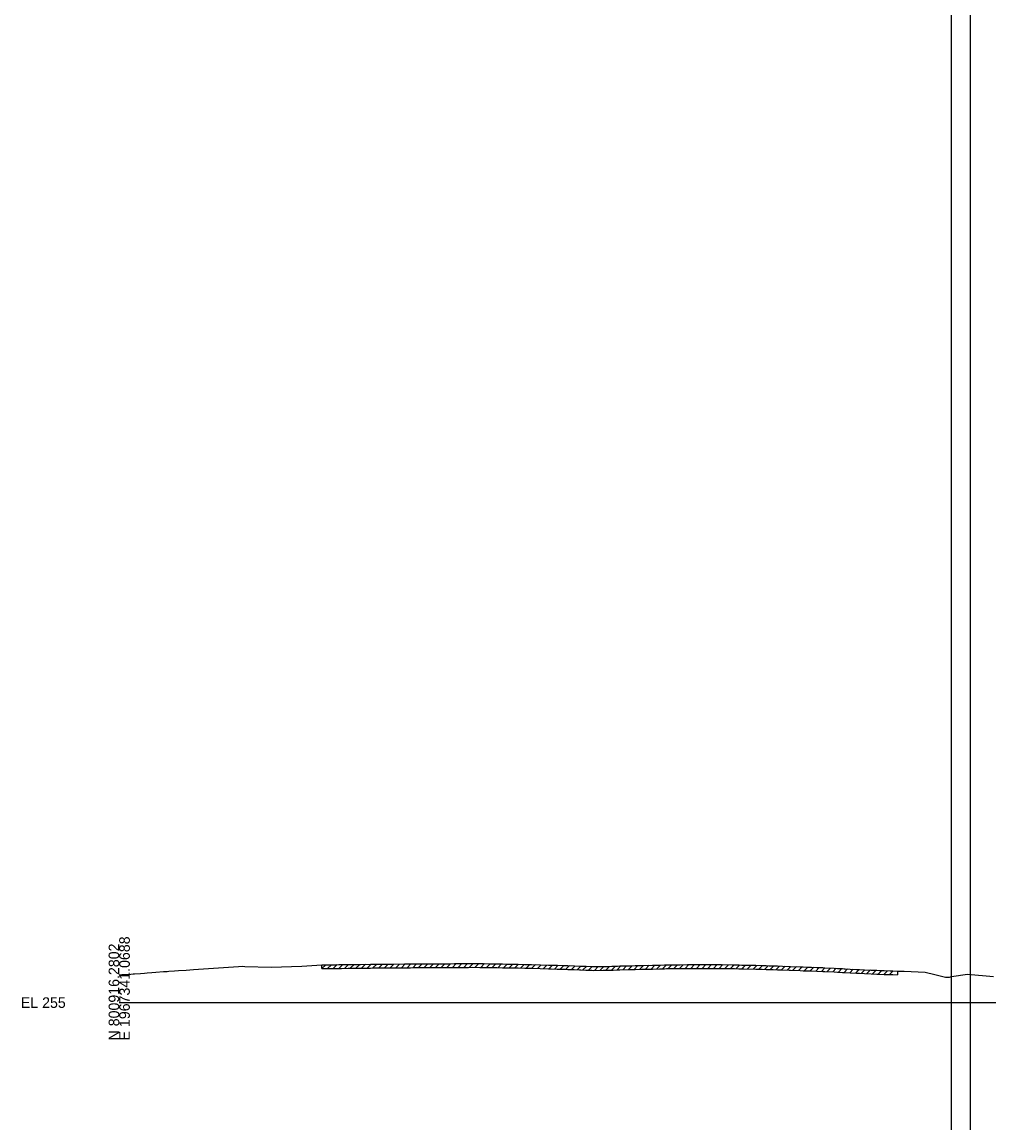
# Model space of a CAD drawing. Extents: x -119 to 6018, y -82 to 34226.
# Drawn here: x -25.7 to 229.9, y 22468.2 to 22759.1 of the extents above; entities that cross this region are included whole.
import ezdxf

# ---------------------------------------------------------------- set-up
doc = ezdxf.new("R2010")
doc.units = 0
for name, color, linetype in [('Default', 7, 'Continuous'), ('RD_GPK_XS_Cell', 7, 'Continuous'), ('RD_Sketch1', 7, 'Continuous'), ('RD_XS_ExGround', 7, 'Continuous'), ('RD_XS_ExPaveRet', 7, 'Continuous')]:
    doc.layers.add(name, color=color, linetype=linetype)

msp = doc.modelspace()

# ---------------------------------------------------------------- linework, layer by layer
at = {"layer": 'RD_GPK_XS_Cell'}
msp.add_line((0, 22500), (300, 22500), dxfattribs=at)
at = {"layer": 'RD_Sketch1'}
for p, q in [((220, -82), (220, 34226.15)), ((225, -82), (225, 34226.15))]:
    msp.add_line(p, q, dxfattribs=at)
at = {"layer": 'RD_XS_ExGround'}
msp.add_lwpolyline([(0, 22507.36), (0.69, 22507.4), (3.08, 22507.55), (3.68, 22507.59), (4, 22507.61), (5.6, 22507.73), (6.65, 22507.81), (7.42, 22507.86), (8.58, 22507.95), (9.66, 22508.04), (11.72, 22508.18), (12.64, 22508.25), (13.13, 22508.28), (14.64, 22508.39), (15.63, 22508.45), (17.67, 22508.59), (18.66, 22508.66), (19.61, 22508.73), (20.98, 22508.82), (31.51, 22509.54), (32.52, 22509.59), (33.24, 22509.57), (40.17, 22509.35), (48.3, 22509.59), (53.57, 22509.98), (53.9, 22509.97), (54.64, 22509.99), (57.52, 22510.02), (58.01, 22510.03), (58.78, 22510.04), (60.48, 22510.06), (61.59, 22510.07), (63.75, 22510.09), (66.39, 22510.14), (66.98, 22510.16), (67.55, 22510.16), (68.69, 22510.18), (69.38, 22510.18), (70.61, 22510.18), (72.45, 22510.18), (75.37, 22510.21), (76.97, 22510.22), (77.8, 22510.24), (78.34, 22510.24), (79.62, 22510.26), (81.53, 22510.26), (84.3, 22510.27), (86.05, 22510.27), (87.3, 22510.28), (88.62, 22510.29), (90.71, 22510.31), (92.3, 22510.32), (93.31, 22510.33), (95.31, 22510.32), (96.29, 22510.3), (98.03, 22510.27), (99.18, 22510.25), (99.84, 22510.24), (101.29, 22510.22), (102.31, 22510.2), (103.18, 22510.18), (104.41, 22510.17), (105.42, 22510.15), (107.18, 22510.11), (108.31, 22510.09), (108.96, 22510.07), (111.21, 22509.99), (113.49, 22509.92), (114.16, 22509.9), (115.75, 22509.86), (117.31, 22509.81), (117.75, 22509.8), (118.54, 22509.79), (120.26, 22509.72), (121.61, 22509.67), (122.02, 22509.64), (123.29, 22509.61), (124.93, 22509.54), (125.29, 22509.51), (127.89, 22509.54), (128.31, 22509.55), (129.37, 22509.58), (130.18, 22509.6), (130.57, 22509.61), (131.68, 22509.67), (132.29, 22509.68), (134.48, 22509.73), (134.9, 22509.74), (135.52, 22509.76), (136.34, 22509.77), (138.11, 22509.81), (140.96, 22509.88), (142.81, 22509.92), (144.1, 22509.95), (144.64, 22509.97), (145.43, 22509.98), (147.09, 22510.01), (148.22, 22510.02), (150.19, 22510.03), (150.59, 22510.03), (153.04, 22510.04), (154.61, 22510.04), (155.46, 22510.04), (156.01, 22510.05), (157.31, 22510.05), (159.2, 22510.05), (161.98, 22509.99), (162.65, 22509.98), (163.73, 22509.95), (164.59, 22509.93), (165.09, 22509.92), (168.22, 22509.85), (169.93, 22509.8), (171, 22509.78), (171.76, 22509.76), (172.86, 22509.73), (174, 22509.69), (175.29, 22509.64), (177.09, 22509.57), (177.39, 22509.56), (179.94, 22509.47), (180.73, 22509.44), (181.91, 22509.4), (182.56, 22509.37), (182.95, 22509.36), (184.34, 22509.31), (185.99, 22509.24), (186.52, 22509.22), (188.94, 22509.09), (189.84, 22509.04), (191.12, 22508.97), (191.56, 22508.94), (191.87, 22508.93), (193.19, 22508.86), (194.87, 22508.77), (195.18, 22508.76), (195.67, 22508.74), (197.01, 22508.68), (198.76, 22508.61), (200.23, 22508.54), (200.97, 22508.51), (202.15, 22508.47), (203.75, 22508.41), (204.45, 22508.39), (205.71, 22508.33), (207.48, 22508.3), (213.02, 22508.04), (215.52, 22507.41), (218.4, 22506.7), (219.42, 22506.7), (219.96, 22506.87), (224.19, 22507.48), (231.1, 22506.89)], dxfattribs=at)
at = {"layer": 'RD_XS_ExPaveRet'}
for p, q in [((53.57, 22508.98), (54.58, 22509.98)), ((53.57, 22508.98), (53.57, 22509.98)), ((55.07, 22508.99), (56.09, 22510.01)), ((56.57, 22509.01), (57.59, 22510.03)), ((58.07, 22509.03), (59.08, 22510.04)), ((59.57, 22509.05), (60.58, 22510.06)), ((61.07, 22509.06), (62.08, 22510.07)), ((62.57, 22509.08), (63.58, 22510.09)), ((64.07, 22509.1), (65.09, 22510.12)), ((65.57, 22509.13), (66.59, 22510.15)), ((67.07, 22509.16), (68.08, 22510.17)), ((68.57, 22509.18), (69.57, 22510.18)), ((70.07, 22509.18), (71.07, 22510.18)), ((71.57, 22509.18), (72.58, 22510.18)), ((73.07, 22509.19), (74.08, 22510.19)), ((74.57, 22509.2), (75.58, 22510.21)), ((76.07, 22509.21), (77.08, 22510.23)), ((77.57, 22509.23), (78.58, 22510.25)), ((79.07, 22509.25), (80.08, 22510.26)), ((80.57, 22509.26), (81.57, 22510.26)), ((82.07, 22509.26), (83.07, 22510.27)), ((83.57, 22509.27), (84.57, 22510.27)), ((85.07, 22509.27), (86.08, 22510.27)), ((86.57, 22509.28), (87.58, 22510.28)), ((88.07, 22509.29), (89.08, 22510.3)), ((89.57, 22509.3), (90.58, 22510.31)), ((91.07, 22509.31), (92.08, 22510.32)), ((92.57, 22509.33), (93.58, 22510.33)), ((94.07, 22509.33), (95.07, 22510.32)), ((95.57, 22509.32), (96.55, 22510.3)), ((97.07, 22509.29), (98.05, 22510.27)), ((98.57, 22509.26), (99.55, 22510.24)), ((100.07, 22509.23), (101.06, 22510.22)), ((101.57, 22509.21), (102.56, 22510.19)), ((103.07, 22509.19), (104.06, 22510.17)), ((104.57, 22509.16), (105.55, 22510.15)), ((106.07, 22509.13), (107.05, 22510.11)), ((107.57, 22509.1), (108.55, 22510.08)), ((109.07, 22509.06), (110.04, 22510.03)), ((110.57, 22509.01), (111.54, 22509.98)), ((143.57, 22508.94), (144.6, 22509.97)), ((145.07, 22508.98), (146.09, 22509.99)), ((146.57, 22509), (147.58, 22510.01)), ((148.07, 22509.02), (149.08, 22510.02)), ((149.57, 22509.03), (150.58, 22510.03)), ((151.07, 22509.03), (152.07, 22510.04)), ((152.57, 22509.04), (153.57, 22510.04)), ((154.07, 22509.04), (155.07, 22510.04)), ((155.57, 22509.04), (156.57, 22510.05)), ((157.07, 22509.05), (158.07, 22510.05)), ((158.57, 22509.05), (159.56, 22510.04)), ((160.07, 22509.03), (161.05, 22510.01)), ((161.57, 22509), (162.55, 22509.98)), ((53.57, 22508.98), (53.9, 22508.97)), ((53.9, 22508.97), (54.64, 22508.99)), ((54.64, 22508.99), (57.52, 22509.02)), ((57.52, 22509.02), (58.01, 22509.03)), ((58.01, 22509.03), (58.78, 22509.04)), ((58.78, 22509.04), (60.48, 22509.06)), ((60.48, 22509.06), (61.59, 22509.07)), ((61.59, 22509.07), (63.75, 22509.09)), ((63.75, 22509.09), (66.39, 22509.14)), ((66.39, 22509.14), (66.98, 22509.16)), ((66.98, 22509.16), (67.55, 22509.16)), ((67.55, 22509.16), (68.69, 22509.18)), ((68.69, 22509.18), (69.38, 22509.18)), ((69.38, 22509.18), (70.61, 22509.18)), ((70.61, 22509.18), (72.45, 22509.18)), ((72.45, 22509.18), (75.37, 22509.21)), ((75.37, 22509.21), (76.97, 22509.22)), ((76.97, 22509.22), (77.8, 22509.24)), ((77.8, 22509.24), (78.34, 22509.24)), ((78.34, 22509.24), (79.62, 22509.26)), ((79.62, 22509.26), (81.53, 22509.26)), ((81.53, 22509.26), (84.3, 22509.27)), ((84.3, 22509.27), (86.05, 22509.27)), ((86.05, 22509.27), (87.3, 22509.28)), ((87.3, 22509.28), (88.62, 22509.29)), ((88.62, 22509.29), (90.71, 22509.31)), ((90.71, 22509.31), (92.3, 22509.32)), ((92.3, 22509.32), (93.31, 22509.33)), ((93.31, 22509.33), (95.31, 22509.32)), ((95.31, 22509.32), (96.29, 22509.3)), ((96.29, 22509.3), (98.03, 22509.27)), ((98.03, 22509.27), (99.18, 22509.25)), ((99.18, 22509.25), (99.84, 22509.24)), ((99.84, 22509.24), (101.29, 22509.21)), ((101.29, 22509.21), (102.31, 22509.2)), ((102.31, 22509.2), (103.18, 22509.18)), ((103.18, 22509.18), (104.41, 22509.17)), ((104.41, 22509.17), (105.42, 22509.15)), ((105.42, 22509.15), (107.18, 22509.11)), ((107.18, 22509.11), (108.31, 22509.09)), ((108.31, 22509.09), (108.96, 22509.07)), ((108.96, 22509.07), (111.21, 22508.99)), ((111.21, 22508.99), (113.49, 22508.92)), ((112.07, 22508.96), (113.04, 22509.93)), ((113.49, 22508.92), (114.16, 22508.9)), ((113.57, 22508.91), (114.54, 22509.89)), ((114.16, 22508.9), (115.75, 22508.86)), ((115.07, 22508.87), (116.05, 22509.85)), ((115.75, 22508.86), (117.31, 22508.81)), ((116.57, 22508.83), (117.54, 22509.81)), ((117.31, 22508.81), (117.75, 22508.8)), ((117.75, 22508.8), (118.54, 22508.79)), ((118.07, 22508.8), (119.04, 22509.77)), ((118.54, 22508.79), (120.26, 22508.72)), ((119.57, 22508.75), (120.54, 22509.71)), ((120.26, 22508.72), (121.61, 22508.67)), ((121.07, 22508.69), (122.02, 22509.64)), ((121.61, 22508.67), (122.02, 22508.64)), ((122.02, 22508.64), (123.29, 22508.61)), ((122.57, 22508.62), (123.55, 22509.6)), ((123.29, 22508.61), (124.93, 22508.54)), ((124.07, 22508.58), (125.03, 22509.53)), ((124.93, 22508.54), (125.29, 22508.51)), ((125.29, 22508.51), (127.89, 22508.54)), ((125.57, 22508.51), (126.58, 22509.52)), ((127.07, 22508.53), (128.08, 22509.54)), ((127.89, 22508.54), (128.31, 22508.55)), ((128.31, 22508.55), (129.37, 22508.58)), ((128.57, 22508.55), (129.6, 22509.58)), ((129.37, 22508.58), (130.18, 22508.6)), ((130.07, 22508.59), (131.12, 22509.64)), ((130.18, 22508.6), (130.57, 22508.61)), ((130.57, 22508.61), (131.68, 22508.67)), ((131.57, 22508.66), (132.6, 22509.69)), ((131.68, 22508.67), (132.29, 22508.68)), ((132.29, 22508.68), (134.48, 22508.73)), ((133.07, 22508.7), (134.09, 22509.72)), ((134.48, 22508.73), (134.9, 22508.74)), ((134.57, 22508.73), (135.6, 22509.76)), ((134.9, 22508.74), (135.52, 22508.76)), ((135.52, 22508.76), (136.34, 22508.77)), ((136.07, 22508.77), (137.09, 22509.79)), ((136.34, 22508.77), (138.11, 22508.81)), ((137.57, 22508.8), (138.59, 22509.82)), ((138.11, 22508.81), (140.96, 22508.88)), ((139.07, 22508.83), (140.1, 22509.86)), ((140.57, 22508.87), (141.6, 22509.89)), ((140.96, 22508.88), (142.81, 22508.92)), ((142.07, 22508.9), (143.1, 22509.93)), ((142.81, 22508.92), (144.1, 22508.95)), ((144.1, 22508.95), (144.64, 22508.97)), ((144.64, 22508.97), (145.43, 22508.98)), ((145.43, 22508.98), (147.09, 22509.01)), ((147.09, 22509.01), (148.22, 22509.02)), ((148.22, 22509.02), (150.19, 22509.03)), ((150.19, 22509.03), (150.59, 22509.03)), ((150.59, 22509.03), (153.04, 22509.04)), ((153.04, 22509.04), (154.61, 22509.04)), ((154.61, 22509.04), (155.46, 22509.04)), ((155.46, 22509.04), (156.01, 22509.05)), ((156.01, 22509.05), (157.31, 22509.05)), ((157.31, 22509.05), (159.2, 22509.05)), ((159.2, 22509.05), (161.98, 22508.99)), ((161.98, 22508.99), (162.65, 22508.98)), ((162.65, 22508.98), (163.73, 22508.95)), ((163.07, 22508.97), (164.05, 22509.95)), ((163.73, 22508.95), (164.59, 22508.93)), ((164.57, 22508.93), (165.55, 22509.91)), ((164.59, 22508.93), (165.09, 22508.92)), ((165.09, 22508.92), (168.22, 22508.85)), ((166.07, 22508.9), (167.05, 22509.87)), ((167.57, 22508.86), (168.55, 22509.84)), ((168.22, 22508.85), (169.93, 22508.8)), ((169.07, 22508.82), (170.05, 22509.8)), ((169.93, 22508.8), (171, 22508.78)), ((170.57, 22508.79), (171.55, 22509.76)), ((171, 22508.78), (171.76, 22508.76)), ((171.76, 22508.76), (172.86, 22508.73)), ((172.07, 22508.75), (173.04, 22509.72)), ((172.86, 22508.73), (174, 22508.69)), ((173.57, 22508.7), (174.54, 22509.67)), ((174, 22508.69), (175.29, 22508.64)), ((175.07, 22508.65), (176.03, 22509.61)), ((175.29, 22508.64), (177.09, 22508.57)), ((176.57, 22508.59), (177.54, 22509.55)), ((177.09, 22508.57), (177.39, 22508.56)), ((177.39, 22508.56), (179.94, 22508.47)), ((178.07, 22508.53), (179.04, 22509.5)), ((179.57, 22508.48), (180.54, 22509.45)), ((179.94, 22508.47), (180.73, 22508.44)), ((180.73, 22508.44), (181.91, 22508.4)), ((181.07, 22508.43), (182.04, 22509.39)), ((181.91, 22508.4), (182.56, 22508.37)), ((182.56, 22508.37), (182.95, 22508.36)), ((182.57, 22508.37), (183.54, 22509.34)), ((182.95, 22508.36), (184.34, 22508.31)), ((184.07, 22508.32), (185.03, 22509.28)), ((184.34, 22508.31), (185.99, 22508.24)), ((185.57, 22508.26), (186.53, 22509.21)), ((185.99, 22508.24), (186.52, 22508.22)), ((186.52, 22508.22), (188.94, 22508.09)), ((187.07, 22508.19), (188.02, 22509.14)), ((188.57, 22508.11), (189.52, 22509.06)), ((188.94, 22508.09), (189.84, 22508.04)), ((189.84, 22508.04), (191.12, 22507.97)), ((190.07, 22508.03), (191.02, 22508.97)), ((191.12, 22507.97), (191.56, 22507.94)), ((191.56, 22507.94), (191.87, 22507.93)), ((191.57, 22507.94), (192.52, 22508.89)), ((191.87, 22507.93), (193.19, 22507.86)), ((193.07, 22507.86), (194.02, 22508.82)), ((193.19, 22507.86), (194.87, 22507.77)), ((194.57, 22507.79), (195.53, 22508.74)), ((194.87, 22507.77), (195.18, 22507.76)), ((195.18, 22507.76), (195.67, 22507.74)), ((195.67, 22507.74), (197.01, 22507.68)), ((196.07, 22507.72), (197.03, 22508.68)), ((197.01, 22507.68), (198.76, 22507.61)), ((197.57, 22507.66), (198.53, 22508.62)), ((198.76, 22507.61), (200.23, 22507.54)), ((199.07, 22507.59), (200.03, 22508.55)), ((200.23, 22507.54), (200.97, 22507.51)), ((200.57, 22507.53), (201.53, 22508.49)), ((200.97, 22507.51), (202.15, 22507.47)), ((202.07, 22507.47), (203.04, 22508.44)), ((202.15, 22507.47), (203.75, 22507.41)), ((203.57, 22507.42), (204.54, 22508.38)), ((203.75, 22507.41), (204.45, 22507.39)), ((204.45, 22507.39), (205.71, 22507.33)), ((205.71, 22508.33), (205.71, 22507.33))]:
    msp.add_line(p, q, dxfattribs=at)

# ---------------------------------------------------------------- texts
at = {"layer": 'Default'}
msp.add_text('-', height=0.0001, dxfattribs=at).set_placement((0, 22500))
at = {"layer": 'RD_GPK_XS_Cell'}
for s, p in [('E 1967341.0688', (2.8, 22490)), ('N 800916.2802', (0, 22490))]:
    msp.add_text(s, height=2.8, rotation=90, dxfattribs=at).set_placement(p)
msp.add_text('EL 255', height=2.8, dxfattribs=at).set_placement((-26, 22498.6))

doc.saveas('drawing.dxf')
